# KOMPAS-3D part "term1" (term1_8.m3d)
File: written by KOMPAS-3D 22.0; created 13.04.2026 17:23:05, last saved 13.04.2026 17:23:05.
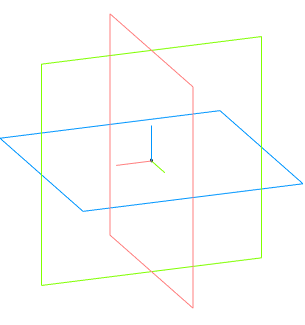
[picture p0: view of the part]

Document properties: Автор: Andrey; Полное имя файла: C:\Users\User1\Documents\term1_8.m3d

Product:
- Part/product: term1

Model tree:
1. Операция без истории:1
